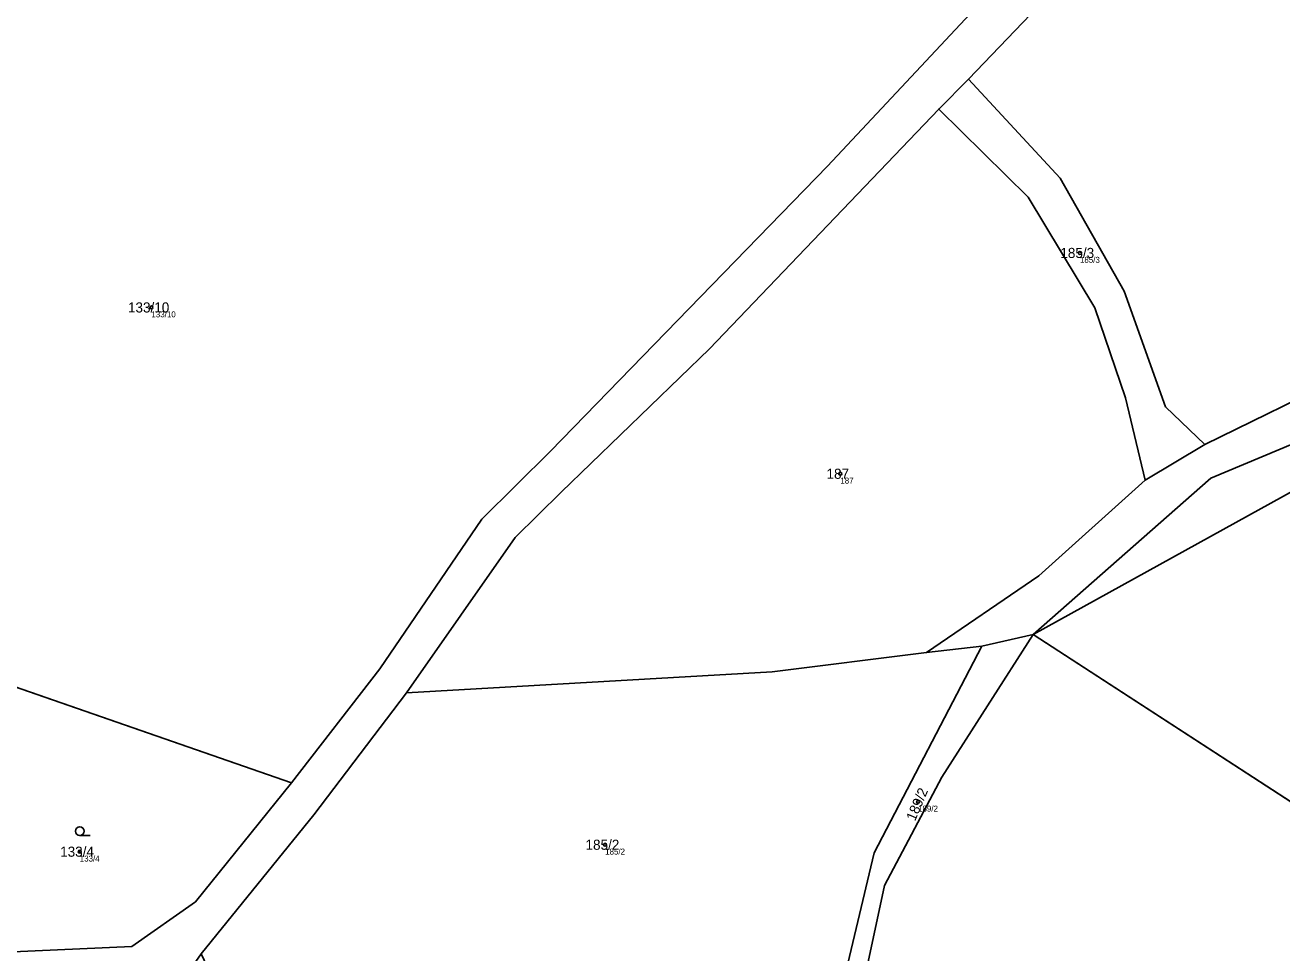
# Model space of a CAD drawing. Extents: x -700238 to -698499, y -1070626 to -1068006.
# Drawn here: x -699762.4 to -699551.1, y -1069066.8 to -1068910.8 of the extents above; entities that cross this region are included whole.
import ezdxf

# ---------------------------------------------------------------- set-up
doc = ezdxf.new("R2010")
doc.units = 0
for name, color, linetype in [('Definiční body', 7, 'Continuous'), ('Hranice parcel', 7, 'Continuous'), ('Parcelní čísla', 7, 'Continuous'), ('Polygon parcely', 7, 'Continuous'), ('Značky kultur', 7, 'Continuous')]:
    doc.layers.add(name, color=color, linetype=linetype)

msp = doc.modelspace()

# ---------------------------------------------------------------- linework, layer by layer
at = {"layer": 'Definiční body'}
for centre in [(-699585.07, -1068949.12994), (-699741.2, -1068958.28994), (-699625.36, -1068986.24994), (-699612.29, -1069041.38994), (-699753.25, -1069049.78994), (-699664.91, -1069048.61994)]:
    msp.add_circle(centre, 0.25, dxfattribs=at)
at = {"layer": 'Hranice parcel'}
for p, q in [((-699608.82, -1068924.95), (-699603.8, -1068919.93)), ((-699564.08, -1068981.34), (-699574.12, -1068987.34)), ((-699601.58, -1069015.24), (-699592.96, -1069013.28)), ((-699592.96, -1069013.28), (-699519.08, -1069061.26)), ((-699717.64, -1069038.19), (-699784.18, -1069015.11)), ((-699610.88, -1069016.29), (-699601.58, -1069015.24))]:
    msp.add_line(p, q, dxfattribs=at)
for points in [[(-699467.03, -1068777.07), (-699469.58, -1068780.23), (-699489.21, -1068798.95), (-699536.5, -1068849.9), (-699549.19, -1068864.03), (-699580.35, -1068895.36), (-699603.8, -1068919.93)], [(-699564.08, -1068981.34), (-699516.89, -1068958.22), (-699501.19, -1068954.74), (-699489.25, -1068955.25), (-699477.59, -1068953.57), (-699466.57, -1068947.54), (-699450.3, -1068923.87), (-699434.9, -1068894.43), (-699437.02, -1068860.08), (-699421.12, -1068856.29), (-699417.46, -1068845.03), (-699436.71, -1068810.63), (-699444.09, -1068780.91)], [(-699601.04, -1068906.25), (-699627.54, -1068934.54), (-699674.11, -1068982.48), (-699685.64, -1068993.9), (-699702.78, -1069019.04), (-699717.64, -1069038.19)], [(-699603.8, -1068919.93), (-699588.42, -1068936.57), (-699577.66, -1068955.53), (-699570.69, -1068974.98), (-699564.08, -1068981.34)], [(-699698.3, -1069023.11), (-699680.05, -1068996.98), (-699672.28, -1068989.32), (-699647.35, -1068965.24), (-699608.82, -1068924.95)], [(-699608.82, -1068924.95), (-699593.8, -1068939.75), (-699582.55, -1068958.34), (-699577.41, -1068973.51), (-699574.12, -1068987.34)], [(-699592.96, -1069013.28), (-699563.08, -1068986.99), (-699548.97, -1068981.12), (-699516.76, -1068963.3), (-699487.89, -1068960.32)], [(-699485.61, -1068969.54), (-699516.76, -1068971.2), (-699592.96, -1069013.28)], [(-699574.12, -1068987.34), (-699592.01, -1069003.42), (-699610.88, -1069016.29)], [(-699622.17, -1069075.39), (-699617.91, -1069055.49), (-699608.3, -1069037.27), (-699592.96, -1069013.28)], [(-699601.58, -1069015.24), (-699619.67, -1069049.99), (-699625.7, -1069075.4)], [(-699610.88, -1069016.29), (-699636.85, -1069019.54), (-699698.3, -1069023.11)], [(-699732.81, -1069066.94), (-699713.87, -1069043.62), (-699698.3, -1069023.11)], [(-699765.76, -1069066.66), (-699744.52, -1069065.73), (-699733.78, -1069058.2), (-699717.64, -1069038.19)]]:
    msp.add_lwpolyline(points, dxfattribs=at)
at = {"layer": 'Polygon parcely'}
for points in [[(-699536.5, -1068849.9), (-699549.19, -1068864.03), (-699580.35, -1068895.36), (-699603.8, -1068919.93), (-699588.42, -1068936.57), (-699577.66, -1068955.53), (-699570.69, -1068974.98), (-699564.08, -1068981.34), (-699516.89, -1068958.22), (-699501.19, -1068954.74), (-699489.25, -1068955.25), (-699477.59, -1068953.57), (-699466.57, -1068947.54), (-699450.3, -1068923.87), (-699434.9, -1068894.43), (-699437.02, -1068860.08), (-699421.12, -1068856.29), (-699417.46, -1068845.03), (-699436.71, -1068810.63), (-699444.09, -1068780.91), (-699467.03, -1068777.07), (-699469.58, -1068780.23), (-699489.21, -1068798.95)], [(-699601.04, -1068906.25), (-699744.81, -1068862.23), (-699871.66, -1068821.49), (-699865.04, -1068834.97), (-699857.58, -1068850.39), (-699844.44, -1068871.08), (-699816.47, -1068910.26), (-699808.84, -1068926.02), (-699798.2, -1068962), (-699790.22, -1068999.77), (-699784.18, -1069015.11), (-699717.64, -1069038.19), (-699702.78, -1069019.04), (-699685.64, -1068993.9), (-699674.11, -1068982.48), (-699627.54, -1068934.54)], [(-699593.8, -1068939.75), (-699582.55, -1068958.34), (-699577.41, -1068973.51), (-699574.12, -1068987.34), (-699564.08, -1068981.34), (-699570.69, -1068974.98), (-699577.66, -1068955.53), (-699588.42, -1068936.57), (-699603.8, -1068919.93), (-699608.82, -1068924.95)], [(-699574.12, -1068987.34), (-699577.41, -1068973.51), (-699582.55, -1068958.34), (-699593.8, -1068939.75), (-699608.82, -1068924.95), (-699647.35, -1068965.24), (-699672.28, -1068989.32), (-699680.05, -1068996.98), (-699698.3, -1069023.11), (-699636.85, -1069019.54), (-699610.88, -1069016.29), (-699592.01, -1069003.42)], [(-699485.61, -1068969.54), (-699487.89, -1068960.32), (-699516.76, -1068963.3), (-699548.97, -1068981.12), (-699563.08, -1068986.99), (-699592.96, -1069013.28), (-699516.76, -1068971.2)], [(-699485.61, -1068969.54), (-699516.76, -1068971.2), (-699592.96, -1069013.28), (-699519.08, -1069061.26), (-699498.04, -1069045.98), (-699462.08, -1069043.15), (-699483.97, -1068974.32)], [(-699619.67, -1069049.99), (-699625.7, -1069075.4), (-699622.17, -1069075.39), (-699617.91, -1069055.49), (-699608.3, -1069037.27), (-699592.96, -1069013.28), (-699601.58, -1069015.24)], [(-699744.52, -1069065.73), (-699733.78, -1069058.2), (-699717.64, -1069038.19), (-699784.18, -1069015.11), (-699768.97, -1069056.9), (-699765.76, -1069066.66)], [(-699698.3, -1069023.11), (-699713.87, -1069043.62), (-699732.81, -1069066.94), (-699731.4, -1069070.03), (-699625.7, -1069075.4), (-699619.67, -1069049.99), (-699601.58, -1069015.24), (-699610.88, -1069016.29), (-699636.85, -1069019.54)]]:
    msp.add_lwpolyline(points, close=True, dxfattribs=at)
for points in [[(-699601.04, -1068906.25), (-699627.54, -1068934.54), (-699674.11, -1068982.48), (-699685.64, -1068993.9), (-699702.78, -1069019.04), (-699717.64, -1069038.19), (-699733.78, -1069058.2), (-699744.52, -1069065.73), (-699765.76, -1069066.66), (-699757.52, -1069092.19), (-699757.47, -1069090.8), (-699752.63, -1069090.86), (-699746.16, -1069083.14), (-699735.67, -1069071.03), (-699732.81, -1069066.94), (-699713.87, -1069043.62), (-699698.3, -1069023.11), (-699680.05, -1068996.98), (-699672.28, -1068989.32), (-699647.35, -1068965.24), (-699608.82, -1068924.95), (-699603.8, -1068919.93), (-699580.35, -1068895.36)], [(-699434.9, -1068894.43), (-699450.3, -1068923.87), (-699466.57, -1068947.54), (-699477.59, -1068953.57), (-699489.25, -1068955.25), (-699501.19, -1068954.74), (-699516.89, -1068958.22), (-699564.08, -1068981.34), (-699574.12, -1068987.34), (-699592.01, -1069003.42), (-699610.88, -1069016.29), (-699601.58, -1069015.24), (-699592.96, -1069013.28), (-699563.08, -1068986.99), (-699548.97, -1068981.12), (-699516.76, -1068963.3), (-699487.89, -1068960.32), (-699474.54, -1068956.68), (-699465.32, -1068952.35), (-699424.37, -1068899.73)], [(-699519.08, -1069061.26), (-699592.96, -1069013.28), (-699608.3, -1069037.27), (-699617.91, -1069055.49), (-699622.17, -1069075.39)]]:
    msp.add_lwpolyline(points, dxfattribs=at)
at = {"layer": 'Značky kultur'}
msp.add_line((-699753.243, -1069047.09), (-699751.493, -1069047.09), dxfattribs=at)
msp.add_circle((-699753.24286, -1069046.33981), 0.75, dxfattribs=at)

# ---------------------------------------------------------------- texts
at = {"layer": 'Definiční body'}
for s, p in [('185/3', (-699585.07, -1068950.786)), ('133/10', (-699741.2, -1068959.946)), ('187', (-699625.36, -1068987.906)), ('189/2', (-699612.29, -1069043.046)), ('185/2', (-699664.91, -1069050.276)), ('133/4', (-699753.25, -1069051.446))]:
    msp.add_text(s, height=0.999996, dxfattribs=at).set_placement(p)
at = {"layer": 'Parcelní čísla'}
for s, p in [('185/3', (-699588.368, -1068949.979)), ('133/10', (-699745.147, -1068959.14)), ('187', (-699627.685, -1068987.1)), ('133/4', (-699756.548, -1069050.64)), ('185/2', (-699668.208, -1069049.47))]:
    msp.add_text(s, height=1.699998, dxfattribs=at).set_placement(p)
msp.add_text('189/2', height=1.699998, rotation=66.9999972, dxfattribs=at).set_placement((-699612.796, -1069044.758))

doc.saveas('drawing.dxf')
